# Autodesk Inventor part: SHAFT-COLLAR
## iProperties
Created: 2008-03
Part Number: SHAFT-COLLAR
Document SubType Name: Modeling
Density: 1 g/cm^3
Mass: 0.517333 g
Surface Area: 4.95075 cm^2
Volume: 0.517333 cm^3
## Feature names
1. Extrusion1
2. Hole1
3. Hole2
